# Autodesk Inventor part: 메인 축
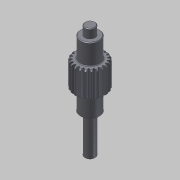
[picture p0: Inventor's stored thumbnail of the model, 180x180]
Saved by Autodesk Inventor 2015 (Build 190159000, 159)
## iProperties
Created: 2016-02
Part Number: 메인 축
Material: 강철, 연강
Document SubType Name: Modeling
Categories: <?xml version="1.0" encoding="UTF-16"?> <MemberInstance><Categories><FamilyTemplate><FamilyTemplateParameter ValueType="xs:double" Id="1" ObjectReferenceKey="da
Density: 7.86 g/cm^3
Appearance: Steel
Mass: 118.054 g
Surface Area: 58.4863 cm^2
Volume: 15.0196 cm^3
CustomPartVersion: 1
Author: mdu
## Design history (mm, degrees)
sketch "Sketch1"
  geometry: C1 r 12 at (0, 0)
  constraints: 1 centre point
  dimensions: "d0" = 24 diameter of C1 (= da_da)
extrude "Extrusion1" new body sketch "Sketch1" distance "d1" = 20 (= da_b); taper "d2" = 0 deg
workplane "Work Plane2"
feature "피치 지름" dims "d4" = 10, "d5" = 0
workplane "Work Plane8"
workplane "Work Plane9"
chamfer "모따기1" distance "d49" = 1; stored, may be unused: second distance "d50" = 2, angle "d51" = 45 deg
sketch "스케치3"
  geometry: C1 r 7.5 at (0, 0); 1 further point
  constraints: 1 centre point, 1 coincident
  dimensions: "d52" = 15 diameter of C1
extrude "돌출2" join sketch "스케치3" distance "d53" = 16; taper "d54" = 0 deg
sketch "스케치4"
  geometry: C1 r 4 at (0, 0); 1 further point
  constraints: 1 centre point, 1 coincident
  dimensions: "d55" = 8 diameter of C1
extrude "돌출3" join sketch "스케치4" distance "d56" = 7; taper "d57" = 0 deg
sketch "스케치5"
  geometry: C1 r 7.5 at (0, 0) reference; C2 r 7.5 at (0, 0) reference; 1 further point
extrude "돌출4" join sketch "스케치5" distance "d62" = 16; taper "d63" = 0 deg
sketch "스케치6"
  geometry: C1 r 4 at (0, 0); 1 further point
  constraints: 1 centre point, 1 coincident
  dimensions: "d64" = 8 diameter of C1
extrude "돌출5" join sketch "스케치6" distance "d65" = 30; taper "d66" = 0 deg
chamfer "모따기2" distance "d58" = 0.5; stored, may be unused: second distance "d59" = 2, angle "d60" = 45 deg
fillet "모깎기1" dims "d61" = 0.5
feature "스퍼 기어" dims "da_b" = 20, "da_d" = 22, "da_aw" = 31, "da_da" = 24, "da_df" = 19.5, "da_dw" = 22, angle "da_beta" = 0 deg, "da_lefttooth" = 0, "da_righttooth" = 0
body "Solid1"
sketch "Sketch2"
  geometry: C1 r 12 at (0, 0) reference; C2 r 11 at (0, 0)
  constraints: 1 centre point, 1 coincident
  dimensions: "d3" = 22 diameter of C2 (= da_dw)
body "Srf1"
node "투영된 루프1"
other parameters: "d16" = 31 (= da_aw), "d17" = 0, "d34" = 1.428 (computed from da_z), "d39" = 0, "d41" = 0, "d43" = 31 (= da_aw), "d46" = 31 (= da_aw), "d47" = 0, "d48" = 0
